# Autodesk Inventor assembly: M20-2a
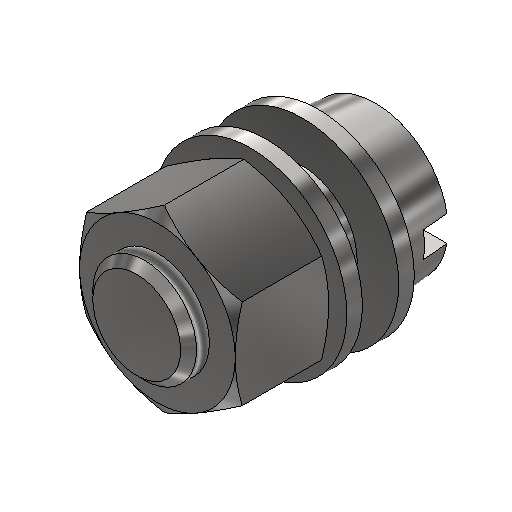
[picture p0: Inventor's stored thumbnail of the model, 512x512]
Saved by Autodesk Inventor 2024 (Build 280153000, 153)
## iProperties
Company: ATC
ClientObjectVersion: 1
Created: 2023-03
Part Number: M20-2a
Document SubType Name: Assembly
Designer: Andrzej Jaskulski
Checked By: A.J.
Engr Approved By: Andrzej Jaskulski
Mfg Approved By: Andrzej Jaskulski
Authority: A.J.
Author: Andrzej Jaskulski
Title: A.J.: Kurs R2024-MEP
Revision Number: 1/24
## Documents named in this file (4)
- C:\Users\AndJas\Documents\R2024-MEP\Obszar roboczy\SPEC\GOTOWE\SPEC-GOTOWE\Design Accelerator\M20-2a.iam
- C:\Users\AndJas\Documents\R2024-MEP\Obszar roboczy\SPEC\GOTOWE\SPEC-GOTOWE\PN\PN-78_M-82005 - 21.ipt
- C:\Users\AndJas\Documents\R2024-MEP\Obszar roboczy\SPEC\GOTOWE\SPEC-GOTOWE\PN\PN-85_M-82215 - M 20 x 35 - 2,5.ipt
- C:\Users\AndJas\Documents\R2024-MEP\Obszar roboczy\SPEC\GOTOWE\SPEC-GOTOWE\PN\PN-86_M-82144 - M20.ipt
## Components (4 placed, 3 different names)
1. PN-78/M-82005 21:1
2. PN-85/M-82215 M 20 x 35:1
3. PN-78/M-82005 21:2
4. PN-86/M-82144 M20:1
